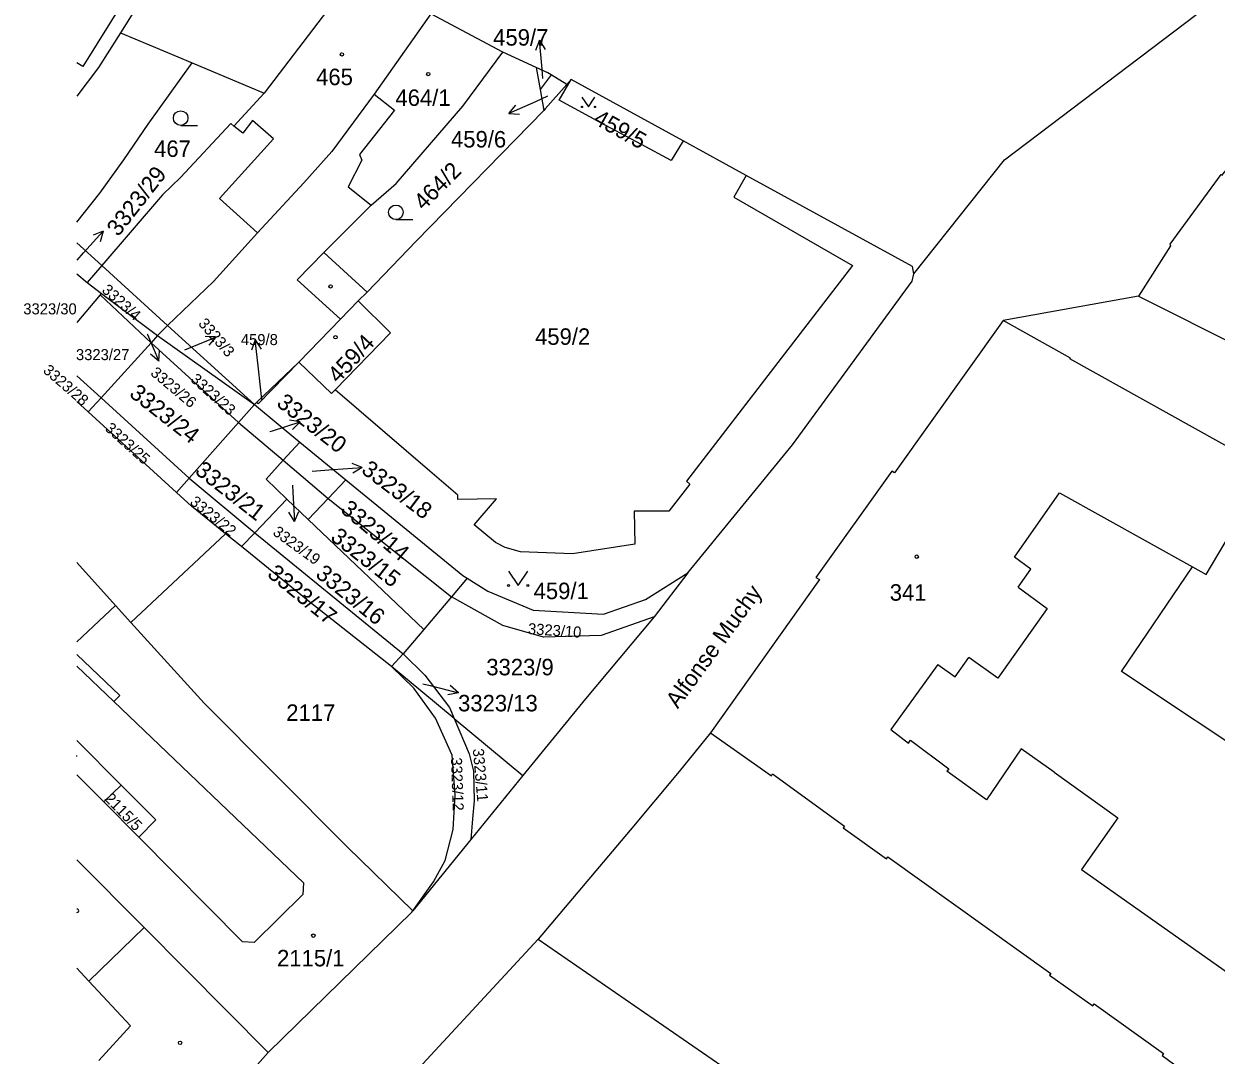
# Model space of a CAD drawing. Extents: x -600849 to -599899, y -1204328 to -1203436.
# Drawn here: x -600848.6 to -600725.7, y -1204227.3 to -1204120.9 of the extents above; entities that cross this region are included whole.
import ezdxf

# ---------------------------------------------------------------- set-up
doc = ezdxf.new("R2010")
doc.units = 0
for name, color, linetype in [('Vrstva 1', 7, 'Continuous'), ('Vrstva 2', 7, 'Continuous'), ('Vrstva 3', 7, 'Continuous'), ('Vrstva 4', 7, 'Continuous'), ('Vrstva 5', 7, 'Continuous'), ('Vrstva 7', 7, 'Continuous')]:
    doc.layers.add(name, color=color, linetype=linetype)

msp = doc.modelspace()

# ---------------------------------------------------------------- linework, layer by layer
at = {"layer": 'Vrstva 1'}
for p, q in [((-600747.51, -1204134.92), (-600717.23, -1204111.96)), ((-600814.59, -1204115.86), (-600823.85, -1204128.03)), ((-600799.24, -1204123.79), (-600806.67, -1204119.86)), ((-600795.8, -1204125.38), (-600799.24, -1204123.79)), ((-600795.8, -1204125.38), (-600795.4, -1204127.65)), ((-600794.24, -1204126.15), (-600795.4, -1204127.65)), ((-600792.64, -1204127.15), (-600794.24, -1204126.15)), ((-600792.17, -1204126.62), (-600792.64, -1204127.15)), ((-600780.62, -1204132.96), (-600792.17, -1204126.62)), ((-600795.4, -1204127.65), (-600795.02, -1204129.82)), ((-600774.13, -1204136.52), (-600780.62, -1204132.96)), ((-600756.86, -1204146.66), (-600747.51, -1204134.92)), ((-600843.16, -1204143.46), (-600840.6, -1204145.81)), ((-600843.16, -1204146.67), (-600842.12, -1204147.58)), ((-600840.6, -1204145.81), (-600842.12, -1204147.58)), ((-600840.6, -1204145.81), (-600833.81, -1204152)), ((-600842.12, -1204147.58), (-600840.63, -1204148.7)), ((-600840.76, -1204148.85), (-600843.16, -1204151.71)), ((-600840.63, -1204148.7), (-600840.76, -1204148.85)), ((-600840.76, -1204148.85), (-600835.5, -1204153.78)), ((-600840.63, -1204148.7), (-600834.84, -1204153.05)), ((-600813.22, -1204148.56), (-600814.15, -1204149.46)), ((-600733.69, -1204148.99), (-600747.63, -1204151.48)), ((-600733.69, -1204148.99), (-600715.88, -1204157.91)), ((-600833.81, -1204152), (-600834.84, -1204153.05)), ((-600833.81, -1204152), (-600824.85, -1204160.17)), ((-600835.5, -1204153.78), (-600840.67, -1204159.47)), ((-600834.84, -1204153.05), (-600835.5, -1204153.78)), ((-600835.5, -1204153.78), (-600826.5, -1204162.03)), ((-600834.84, -1204153.05), (-600824.85, -1204160.17)), ((-600824.63, -1204159.96), (-600820.29, -1204155.8)), ((-600843.16, -1204157.2), (-600840.67, -1204159.47)), ((-600841.99, -1204160.92), (-600843.16, -1204159.85)), ((-600840.67, -1204159.47), (-600841.99, -1204160.92)), ((-600840.67, -1204159.47), (-600831.57, -1204167.75)), ((-600824.85, -1204160.17), (-600826.5, -1204162.03)), ((-600824.63, -1204159.96), (-600824.85, -1204160.17)), ((-600824.85, -1204160.17), (-600820.16, -1204164.03)), ((-600832.89, -1204169.23), (-600841.99, -1204160.92)), ((-600826.5, -1204162.03), (-600831.57, -1204167.75)), ((-600826.5, -1204162.03), (-600821.88, -1204165.91)), ((-600820.16, -1204164.03), (-600821.88, -1204165.91)), ((-600820.16, -1204164.03), (-600815.42, -1204167.92)), ((-600821.88, -1204165.91), (-600817.25, -1204169.84)), ((-600831.57, -1204167.75), (-600832.89, -1204169.23)), ((-600831.57, -1204167.75), (-600824.82, -1204173.39)), ((-600815.42, -1204167.92), (-600817.25, -1204169.84)), ((-600821.51, -1204169.92), (-600824.82, -1204173.39)), ((-600819.32, -1204172.02), (-600821.51, -1204169.92)), ((-600817.25, -1204169.84), (-600819.32, -1204172.02)), ((-600817.25, -1204169.84), (-600804.54, -1204180)), ((-600819.32, -1204172.02), (-600807.38, -1204183.36)), ((-600827.84, -1204173.49), (-600837.61, -1204182.64)), ((-600826.19, -1204174.82), (-600827.84, -1204173.49)), ((-600824.82, -1204173.39), (-600826.19, -1204174.82)), ((-600824.82, -1204173.39), (-600809.52, -1204185.89)), ((-600802.92, -1204178.08), (-600804.54, -1204180)), ((-600780.16, -1204177.54), (-600783.64, -1204182.07)), ((-600837.61, -1204182.64), (-600839.17, -1204180.91)), ((-600804.54, -1204180), (-600807.38, -1204183.36)), ((-600807.38, -1204183.36), (-600809.52, -1204185.89)), ((-600809.52, -1204185.89), (-600810.71, -1204187.19)), ((-600804.27, -1204192.54), (-600810.71, -1204187.19)), ((-600804.27, -1204192.54), (-600797.17, -1204198.43)), ((-600777.81, -1204194.03), (-600771.54, -1204198.47)), ((-600838.59, -1204199.42), (-600843.16, -1204194.83)), ((-600797.17, -1204198.43), (-600802.55, -1204205.03)), ((-600802.55, -1204205.03), (-600808.51, -1204212.4)), ((-600823.44, -1204227.01), (-600808.63, -1204212.53)), ((-600808.63, -1204212.53), (-600808.51, -1204212.4)), ((-600818.26, -1204239.83), (-600795.58, -1204215.31))]:
    msp.add_line(p, q, dxfattribs=at)
for points in [[(-600835.83, -1204117.26), (-600838.68, -1204121.81), (-600840.92, -1204125.39)], [(-600806.67, -1204119.86), (-600812.52, -1204128.13), (-600816.88, -1204134.04), (-600819.75, -1204137.27), (-600824.52, -1204142.43), (-600829.08, -1204147.45), (-600833.81, -1204152)], [(-600813.22, -1204148.56), (-600817.7, -1204144.49), (-600812.81, -1204139.6), (-600810.25, -1204137.36), (-600803.35, -1204129.36), (-600799.24, -1204123.79)], [(-600843.16, -1204141.34), (-600840.8, -1204138.34), (-600838.31, -1204134.91), (-600835.82, -1204131.24), (-600831.27, -1204124.92), (-600823.85, -1204128.03)], [(-600840.92, -1204125.39), (-600843.16, -1204128.35)], [(-600794.24, -1204126.15), (-600794.58, -1204125.94), (-600795.8, -1204125.38)], [(-600780.62, -1204132.96), (-600781.87, -1204134.97), (-600784.95, -1204133.34), (-600788.69, -1204131.34), (-600793.43, -1204128.76), (-600792.17, -1204126.62)], [(-600823.85, -1204128.03), (-600826.97, -1204131.43), (-600827.29, -1204131.16), (-600832.48, -1204136.73), (-600834.35, -1204138.53), (-600840.6, -1204145.81)], [(-600792.64, -1204127.15), (-600794.88, -1204129.65), (-600795.02, -1204129.82)], [(-600795.02, -1204129.82), (-600808.18, -1204143.32), (-600813.22, -1204148.56)], [(-600719.1, -1204133.63), (-600721.32, -1204131.85), (-600725.11, -1204136.53), (-600725.18, -1204136.42), (-600730.46, -1204143.62), (-600730.37, -1204143.77), (-600733.69, -1204148.99)], [(-600774.13, -1204136.52), (-600775.42, -1204138.75), (-600763.16, -1204145.82), (-600780.3, -1204168.08), (-600779.94, -1204168.36), (-600782.13, -1204171.17), (-600785.7, -1204171.17), (-600785.63, -1204174.56), (-600792.06, -1204175.55), (-600797.42, -1204175.36), (-600798.99, -1204174.91), (-600799.98, -1204174.41), (-600802.18, -1204172.58), (-600799.88, -1204169.88), (-600803.88, -1204169.97), (-600803.89, -1204169.52), (-600806.76, -1204167.02), (-600816.53, -1204158.65)], [(-600756.86, -1204146.66), (-600757, -1204145.93), (-600774.13, -1204136.52)], [(-600780.16, -1204177.54), (-600769.37, -1204164.31), (-600757.03, -1204147.43), (-600756.86, -1204146.66)], [(-600814.15, -1204149.46), (-600815.99, -1204151.36), (-600820.29, -1204155.8)], [(-600814.15, -1204149.46), (-600810.82, -1204152.76), (-600816.53, -1204158.65)], [(-600747.63, -1204151.48), (-600758.83, -1204167.22), (-600759.13, -1204167.04), (-600766.94, -1204178.01), (-600766.57, -1204178.22), (-600777.81, -1204194.03)], [(-600720.28, -1204166.85), (-600740.76, -1204155.46), (-600740.7, -1204155.38), (-600747.63, -1204151.48)], [(-600820.29, -1204155.8), (-600824.48, -1204160.09), (-600824.63, -1204159.96)], [(-600816.53, -1204158.65), (-600816.9, -1204159.01), (-600820.29, -1204155.8)], [(-600821.88, -1204165.91), (-600823.65, -1204167.86), (-600821.51, -1204169.92)], [(-600705.74, -1204207.34), (-600710.47, -1204204.44), (-600720.12, -1204197.88), (-600735.42, -1204187.71), (-600728.12, -1204176.9), (-600726.69, -1204177.69), (-600720.28, -1204166.85)], [(-600815.42, -1204167.92), (-600803.37, -1204177.8), (-600802.92, -1204178.08)], [(-600827.84, -1204173.49), (-600831.33, -1204170.66), (-600832.89, -1204169.23)], [(-600810.71, -1204187.19), (-600819.15, -1204180.55), (-600826.19, -1204174.82)], [(-600839.17, -1204180.91), (-600843.16, -1204176.46)], [(-600802.92, -1204178.08), (-600800.77, -1204179.43), (-600796.09, -1204181.38), (-600788.84, -1204181.8), (-600784.52, -1204180.28), (-600780.16, -1204177.54)], [(-600839.17, -1204180.91), (-600843.16, -1204184.65)], [(-600783.64, -1204182.07), (-600789.11, -1204183.99), (-600795.04, -1204184.15), (-600799.25, -1204182.95), (-600804.54, -1204180)], [(-600783.64, -1204182.07), (-600790.72, -1204190.51), (-600797.17, -1204198.43)], [(-600808.51, -1204212.4), (-600815.29, -1204205.78), (-600830.04, -1204190.97), (-600837.61, -1204182.64)], [(-600809.52, -1204185.89), (-600807.28, -1204188.08), (-600804.75, -1204191.41), (-600804.27, -1204192.54)], [(-600843.16, -1204187.16), (-600839.36, -1204190.8), (-600819.8, -1204209.52), (-600819.85, -1204210.7), (-600824.88, -1204215.65), (-600826.09, -1204215.61), (-600836.77, -1204204.8)], [(-600808.51, -1204212.4), (-600806.39, -1204209.4), (-600805.17, -1204207.22), (-600804.34, -1204204.02), (-600804.14, -1204200.44), (-600804.45, -1204196.33), (-600806.17, -1204192.52), (-600808.43, -1204189.42), (-600810.71, -1204187.19)], [(-600804.27, -1204192.54), (-600802.7, -1204196.2), (-600802.26, -1204197.99), (-600802.18, -1204201.06), (-600802.36, -1204202.89), (-600802.55, -1204205.03)], [(-600777.81, -1204194.03), (-600781.06, -1204198.02), (-600786.1, -1204204.06), (-600795.58, -1204215.31)], [(-600771.54, -1204198.47), (-600771.41, -1204198.27), (-600764, -1204203.66)], [(-600836.77, -1204204.8), (-600840.4, -1204201.15), (-600838.59, -1204199.42)], [(-600838.59, -1204199.42), (-600835.03, -1204203.01), (-600836.77, -1204204.8)], [(-600764, -1204203.66), (-600764.12, -1204203.84), (-600759.65, -1204207.05), (-600759.52, -1204206.84), (-600742.73, -1204218.85), (-600742.85, -1204219.05), (-600738.39, -1204222.21), (-600738.26, -1204222.01), (-600731.11, -1204227.12), (-600731.23, -1204227.31), (-600724.97, -1204231.92), (-600724.82, -1204231.68)], [(-600823.44, -1204227.01), (-600836.22, -1204214.11), (-600843.16, -1204207.13)], [(-600795.58, -1204215.31), (-600751.72, -1204245.58), (-600746.31, -1204249.42)], [(-600835.26, -1204240.11), (-600835.16, -1204240.22), (-600823.44, -1204227.01)]]:
    msp.add_lwpolyline(points, dxfattribs=at)
at = {"layer": 'Vrstva 3'}
for p, q in [((-600832.46, -1204131.36), (-600830.71, -1204131.36)), ((-600810.26, -1204141.08), (-600808.51, -1204141.08))]:
    msp.add_line(p, q, dxfattribs=at)
for points in [[(-600791.07, -1204128.44), (-600790.4, -1204129.45), (-600789.73, -1204128.44)], [(-600798.66, -1204177.34), (-600797.66, -1204178.84), (-600796.66, -1204177.34)]]:
    msp.add_lwpolyline(points, dxfattribs=at)
for centre, radius in [((-600791.07, -1204129.45), 0.067), ((-600789.73, -1204129.45), 0.067), ((-600832.46, -1204130.61), 0.75), ((-600810.26, -1204140.33), 0.75), ((-600798.66, -1204178.84), 0.1), ((-600796.66, -1204178.84), 0.1)]:
    msp.add_circle(centre, radius, dxfattribs=at)
at = {"layer": 'Vrstva 4'}
for p, q in [((-600837.99, -1204117.94), (-600842.55, -1204125.3)), ((-600838.68, -1204121.81), (-600831.27, -1204124.92)), ((-600842.55, -1204125.3), (-600843.16, -1204124.9)), ((-600812.52, -1204128.13), (-600810.4, -1204129.8)), ((-600810.4, -1204129.8), (-600814.01, -1204134.36)), ((-600826.04, -1204132.15), (-600826.97, -1204131.43)), ((-600825.06, -1204130.84), (-600826.04, -1204132.15)), ((-600822.9, -1204132.74), (-600825.06, -1204130.84)), ((-600828.45, -1204138.89), (-600822.9, -1204132.74)), ((-600814.01, -1204134.36), (-600813.76, -1204134.96)), ((-600813.76, -1204134.96), (-600815.19, -1204137.69)), ((-600815.19, -1204137.69), (-600812.81, -1204139.6)), ((-600824.52, -1204142.43), (-600828.45, -1204138.89)), ((-600817.7, -1204144.49), (-600820.44, -1204147.28)), ((-600820.44, -1204147.28), (-600815.99, -1204151.36)), ((-600746.47, -1204175.91), (-600741.81, -1204169.27)), ((-600741.81, -1204169.27), (-600728.12, -1204176.9)), ((-600744.77, -1204177.16), (-600746.47, -1204175.91)), ((-600746.08, -1204179.01), (-600744.77, -1204177.16)), ((-600746.08, -1204179.01), (-600743.09, -1204181.2)), ((-600743.09, -1204181.2), (-600748.2, -1204188.38)), ((-600843.16, -1204185.94), (-600838.74, -1204190.18)), ((-600754.36, -1204186.97), (-600759.21, -1204193.69)), ((-600754.36, -1204186.97), (-600752.58, -1204188.25)), ((-600752.58, -1204188.25), (-600751.19, -1204186.27)), ((-600748.2, -1204188.38), (-600751.19, -1204186.27)), ((-600838.74, -1204190.18), (-600839.36, -1204190.8)), ((-600759.21, -1204193.69), (-600757.39, -1204195.09)), ((-600757.39, -1204195.09), (-600757.19, -1204194.78)), ((-600757.19, -1204194.78), (-600753.24, -1204197.76)), ((-600745.76, -1204195.67), (-600749.36, -1204200.96)), ((-600742.39, -1204198.1), (-600745.76, -1204195.67)), ((-600843.16, -1204198.38), (-600840.4, -1204201.15)), ((-600753.24, -1204197.76), (-600753.43, -1204197.99)), ((-600749.36, -1204200.96), (-600753.43, -1204197.99)), ((-600742.39, -1204198.1), (-600735.82, -1204202.81)), ((-600735.82, -1204202.81), (-600739.54, -1204208.14)), ((-600739.54, -1204208.14), (-600723.91, -1204219.16)), ((-600841.94, -1204219.65), (-600836.22, -1204214.11)), ((-600843.16, -1204218.32), (-600841.94, -1204219.65)), ((-600841.94, -1204219.65), (-600837.65, -1204224.28)), ((-600840.9, -1204227.83), (-600837.65, -1204224.28))]:
    msp.add_line(p, q, dxfattribs=at)
at = {"layer": 'Vrstva 5'}
for centre in [(-600815.83, -1204124.04), (-600806.93, -1204126.07), (-600817, -1204147.97), (-600816.49, -1204153.22), (-600756.55, -1204175.86), (-600818.78, -1204214.96), (-600832.52, -1204226.02)]:
    msp.add_circle(centre, 0.175, dxfattribs=at)
for centre, start, end in [((-600843.33, -1204196.43), 342.3909, 17.6091), ((-600843.13, -1204212.39), 259.0639, 100.9361)]:
    msp.add_arc(centre, 0.175, start, end, dxfattribs=at)
at = {"layer": 'Vrstva 7'}
for p, q in [((-600795.45, -1204122.58), (-600795.86, -1204123.62)), ((-600795.19, -1204125.57), (-600795.45, -1204122.58)), ((-600795.45, -1204122.58), (-600794.86, -1204123.53)), ((-600795.11, -1204126.51), (-600795.19, -1204125.57)), ((-600795.88, -1204128.92), (-600798.62, -1204130.14)), ((-600798.62, -1204130.14), (-600797.91, -1204129.28)), ((-600794.63, -1204128.35), (-600795.88, -1204128.92)), ((-600798.62, -1204130.14), (-600797.5, -1204130.19)), ((-600842.47, -1204144.52), (-600840.46, -1204142.29)), ((-600840.46, -1204142.29), (-600841.5, -1204142.7)), ((-600840.46, -1204142.29), (-600840.76, -1204143.37)), ((-600843.15, -1204145.27), (-600842.47, -1204144.52)), ((-600835.91, -1204152.87), (-600835.88, -1204152.94)), ((-600835.88, -1204152.94), (-600834.71, -1204155.7)), ((-600831.61, -1204154.34), (-600828.83, -1204153.22)), ((-600828.83, -1204153.22), (-600829.94, -1204153.13)), ((-600828.83, -1204153.22), (-600829.57, -1204154.05)), ((-600824.76, -1204153.5), (-600825.16, -1204154.54)), ((-600824.45, -1204156.48), (-600824.76, -1204153.5)), ((-600824.76, -1204153.5), (-600824.16, -1204154.44)), ((-600834.71, -1204155.7), (-600835.56, -1204154.98)), ((-600834.71, -1204155.7), (-600834.64, -1204154.58)), ((-600832.04, -1204154.51), (-600831.61, -1204154.34)), ((-600824.1, -1204159.65), (-600824.45, -1204156.48)), ((-600822.99, -1204162.88), (-600820.14, -1204161.95)), ((-600820.14, -1204161.95), (-600821.24, -1204161.79)), ((-600820.14, -1204161.95), (-600820.93, -1204162.74)), ((-600823.25, -1204162.96), (-600822.99, -1204162.88)), ((-600813.75, -1204166.66), (-600814.78, -1204166.23)), ((-600818.9, -1204167.03), (-600816.74, -1204166.87)), ((-600816.74, -1204166.87), (-600813.75, -1204166.66)), ((-600813.75, -1204166.66), (-600814.71, -1204167.23)), ((-600820.93, -1204168.49), (-600820.89, -1204169.23)), ((-600820.89, -1204169.23), (-600820.73, -1204172.23)), ((-600820.73, -1204172.23), (-600821.29, -1204171.25)), ((-600820.73, -1204172.23), (-600820.29, -1204171.2)), ((-600807.49, -1204188.97), (-600806.73, -1204189.16)), ((-600806.73, -1204189.16), (-600803.82, -1204189.89)), ((-600803.82, -1204189.89), (-600804.67, -1204189.16)), ((-600803.82, -1204189.89), (-600804.91, -1204190.13))]:
    msp.add_line(p, q, dxfattribs=at)

# ---------------------------------------------------------------- texts
at = {"layer": 'Vrstva 2'}
for s, height, p in [('459/7', 1.7, (-600800.23, -1204123.13)), ('465', 1.7, (-600818.49, -1204127.21)), ('464/1', 1.7, (-600810.31, -1204129.35)), ('459/6', 1.7, (-600804.58, -1204133.64)), ('467', 1.7, (-600835.2, -1204134.61)), ('3323/30', 1.14, (-600848.69, -1204150.86)), ('459/8', 1.139, (-600826.25, -1204154.03)), ('459/2', 1.7, (-600795.91, -1204154)), ('3323/27', 1.14, (-600843.26, -1204155.58)), ('459/1', 1.7, (-600796.06, -1204180.24)), ('341', 1.7, (-600759.33, -1204180.4)), ('3323/9', 1.7, (-600800.94, -1204188.1)), ('3323/13', 1.7, (-600803.85, -1204191.82)), ('2117', 1.7, (-600821.57, -1204192.8)), ('2115/1', 1.7, (-600822.52, -1204218.13))]:
    msp.add_text(s, height=height, dxfattribs=at).set_placement(p)
for s, height, rotation, p in [('459/5', 1.7, 331, (-600790.02, -1204131.11)), ('3323/29', 1.7, 52, (-600838.89, -1204142.91)), ('464/2', 1.7, 45, (-600807.4, -1204140.21)), ('3323/4', 1.14, 318, (-600840.67, -1204148.47)), ('3323/3', 1.139, 311, (-600830.71, -1204151.85)), ('459/4', 1.7, 47, (-600816.22, -1204158.06)), ('3323/28', 1.14, 319, (-600846.74, -1204156.77)), ('3323/26', 1.14, 320, (-600835.66, -1204157.04)), ('3323/23', 1.14, 318, (-600831.53, -1204157.68)), ('3323/24', 1.7, 322, (-600837.86, -1204159.24)), ('3323/20', 1.7, 322, (-600822.68, -1204160.22)), ('3323/25', 1.14, 318, (-600840.35, -1204162.74)), ('3323/21', 1.7, 322, (-600831.09, -1204167.2)), ('3323/18', 1.7, 323, (-600813.93, -1204167.14)), ('3323/22', 1.14, 321, (-600831.59, -1204170.37)), ('3323/14', 1.7, 320, (-600816.08, -1204171.16)), ('3323/19', 1.14, 324, (-600823.05, -1204173.53)), ('3323/15', 1.7, 322, (-600817.12, -1204174.06)), ('3323/17', 1.7, 321, (-600823.63, -1204177.83)), ('3323/16', 1.7, 321, (-600818.66, -1204177.85)), ('3323/10', 1.14, 356, (-600796.67, -1204183.84)), ('3323/11', 1.14, 275, (-600802.34, -1204195.7)), ('3323/12', 1.14, 272, (-600804.59, -1204196.59)), ('2115/5', 1.14, 314, (-600840.38, -1204200.9))]:
    msp.add_text(s, height=height, rotation=rotation, dxfattribs=at).set_placement(p)
at = {"layer": 'Vrstva 7'}
msp.add_text('Alfonse Muchy', height=1.7, rotation=54, dxfattribs=at).set_placement((-600781.19, -1204191.62))

doc.saveas('drawing.dxf')
